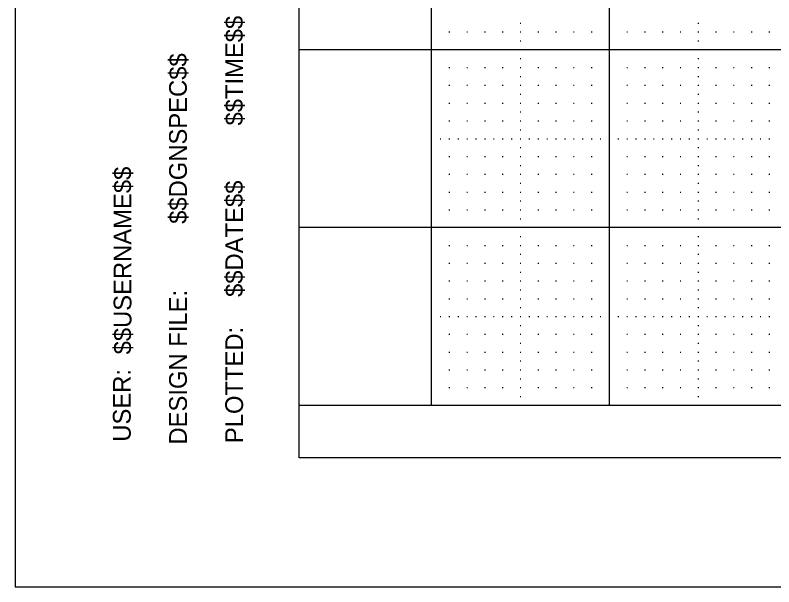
# Model space of a CAD drawing. Extents: x -1.6 to 32.4, y -0.7 to 21.3.
# Drawn here: x -1.598 to 2.67, y -0.727 to 2.487 of the extents above; entities that cross this region are included whole.
import ezdxf

# ---------------------------------------------------------------- set-up
doc = ezdxf.new("R2010")
doc.units = 0
for name, color, linetype in [('Level 1', 7, 'Continuous'), ('Level 4', 7, 'Continuous'), ('Level 5', 7, 'Continuous'), ('Level 63', 7, 'Continuous'), ('R_Border_Dark', 7, 'Continuous')]:
    doc.layers.add(name, color=color, linetype=linetype)

msp = doc.modelspace()

# ---------------------------------------------------------------- linework, layer by layer
at = {"layer": 'Level 1'}
for p, q in [((-0.001, -0.001), (-0.001, 20.545)), ((31.617, -0.001), (-0.001, -0.001))]:
    msp.add_line(p, q, dxfattribs=at)
at = {"layer": 'Level 4'}
msp.add_line((31.617, 0.293), (-0.001, 0.293), dxfattribs=at)
at = {"layer": 'Level 5'}
for p, q in [((1.2425, 2.443), (1.2475, 2.443)), ((2.2425, 2.443), (2.2475, 2.443)), ((0.8425, 2.393), (0.8475, 2.393)), ((0.9425, 2.393), (0.9475, 2.393)), ((1.0425, 2.393), (1.0475, 2.393)), ((1.1425, 2.393), (1.1475, 2.393)), ((1.2425, 2.393), (1.2475, 2.393)), ((1.3425, 2.393), (1.3475, 2.393)), ((1.4425, 2.393), (1.4475, 2.393)), ((1.5425, 2.393), (1.5475, 2.393)), ((1.6425, 2.393), (1.6475, 2.393)), ((1.8425, 2.393), (1.8475, 2.393)), ((1.9425, 2.393), (1.9475, 2.393)), ((2.0425, 2.393), (2.0475, 2.393)), ((2.1425, 2.393), (2.1475, 2.393)), ((2.2425, 2.393), (2.2475, 2.393)), ((2.3425, 2.393), (2.3475, 2.393)), ((2.4425, 2.393), (2.4475, 2.393)), ((2.5425, 2.393), (2.5475, 2.393)), ((2.6425, 2.393), (2.6475, 2.393)), ((1.2425, 2.343), (1.2475, 2.343)), ((2.2425, 2.343), (2.2475, 2.343)), ((1.2425, 2.243), (1.2475, 2.243)), ((2.2425, 2.243), (2.2475, 2.243)), ((0.8425, 2.193), (0.8475, 2.193)), ((0.9425, 2.193), (0.9475, 2.193)), ((1.0425, 2.193), (1.0475, 2.193)), ((1.1425, 2.193), (1.1475, 2.193)), ((1.2425, 2.193), (1.2475, 2.193)), ((1.3425, 2.193), (1.3475, 2.193)), ((1.4425, 2.193), (1.4475, 2.193)), ((1.5425, 2.193), (1.5475, 2.193)), ((1.6425, 2.193), (1.6475, 2.193)), ((1.8425, 2.193), (1.8475, 2.193)), ((1.9425, 2.193), (1.9475, 2.193)), ((2.0425, 2.193), (2.0475, 2.193)), ((2.1425, 2.193), (2.1475, 2.193)), ((2.2425, 2.193), (2.2475, 2.193)), ((2.3425, 2.193), (2.3475, 2.193)), ((2.4425, 2.193), (2.4475, 2.193)), ((2.5425, 2.193), (2.5475, 2.193)), ((2.6425, 2.193), (2.6475, 2.193)), ((1.2425, 2.143), (1.2475, 2.143)), ((2.2425, 2.143), (2.2475, 2.143)), ((0.8425, 2.093), (0.8475, 2.093)), ((0.9425, 2.093), (0.9475, 2.093)), ((1.0425, 2.093), (1.0475, 2.093)), ((1.1425, 2.093), (1.1475, 2.093)), ((1.2425, 2.093), (1.2475, 2.093)), ((1.3425, 2.093), (1.3475, 2.093)), ((1.4425, 2.093), (1.4475, 2.093)), ((1.5425, 2.093), (1.5475, 2.093)), ((1.6425, 2.093), (1.6475, 2.093)), ((1.8425, 2.093), (1.8475, 2.093)), ((1.9425, 2.093), (1.9475, 2.093)), ((2.0425, 2.093), (2.0475, 2.093)), ((2.1425, 2.093), (2.1475, 2.093)), ((2.2425, 2.093), (2.2475, 2.093)), ((2.3425, 2.093), (2.3475, 2.093)), ((2.4425, 2.093), (2.4475, 2.093)), ((2.5425, 2.093), (2.5475, 2.093)), ((2.6425, 2.093), (2.6475, 2.093)), ((1.2425, 2.043), (1.2475, 2.043)), ((2.2425, 2.043), (2.2475, 2.043)), ((0.8425, 1.993), (0.8475, 1.993)), ((0.9425, 1.993), (0.9475, 1.993)), ((1.0425, 1.993), (1.0475, 1.993)), ((1.1425, 1.993), (1.1475, 1.993)), ((1.2425, 1.993), (1.2475, 1.993)), ((1.3425, 1.993), (1.3475, 1.993)), ((1.4425, 1.993), (1.4475, 1.993)), ((1.5425, 1.993), (1.5475, 1.993)), ((1.6425, 1.993), (1.6475, 1.993)), ((1.8425, 1.993), (1.8475, 1.993)), ((1.9425, 1.993), (1.9475, 1.993)), ((2.0425, 1.993), (2.0475, 1.993)), ((2.1425, 1.993), (2.1475, 1.993)), ((2.2425, 1.993), (2.2475, 1.993)), ((2.3425, 1.993), (2.3475, 1.993)), ((2.4425, 1.993), (2.4475, 1.993)), ((2.5425, 1.993), (2.5475, 1.993)), ((2.6425, 1.993), (2.6475, 1.993)), ((1.2425, 1.943), (1.2475, 1.943)), ((2.2425, 1.943), (2.2475, 1.943)), ((0.8425, 1.893), (0.8475, 1.893)), ((0.9425, 1.893), (0.9475, 1.893)), ((1.0425, 1.893), (1.0475, 1.893)), ((1.1425, 1.893), (1.1475, 1.893)), ((1.2425, 1.893), (1.2475, 1.893)), ((1.3425, 1.893), (1.3475, 1.893)), ((1.4425, 1.893), (1.4475, 1.893)), ((1.5425, 1.893), (1.5475, 1.893)), ((1.6425, 1.893), (1.6475, 1.893)), ((1.8425, 1.893), (1.8475, 1.893)), ((1.9425, 1.893), (1.9475, 1.893)), ((2.0425, 1.893), (2.0475, 1.893)), ((2.1425, 1.893), (2.1475, 1.893)), ((2.2425, 1.893), (2.2475, 1.893)), ((2.3425, 1.893), (2.3475, 1.893)), ((2.4425, 1.893), (2.4475, 1.893)), ((2.5425, 1.893), (2.5475, 1.893)), ((2.6425, 1.893), (2.6475, 1.893)), ((1.2425, 1.843), (1.2475, 1.843)), ((2.2425, 1.843), (2.2475, 1.843)), ((0.7925, 1.793), (0.7975, 1.793)), ((0.8425, 1.793), (0.8475, 1.793)), ((0.8925, 1.793), (0.8975, 1.793)), ((0.9425, 1.793), (0.9475, 1.793)), ((0.9925, 1.793), (0.9975, 1.793)), ((1.0425, 1.793), (1.0475, 1.793)), ((1.0925, 1.793), (1.0975, 1.793)), ((1.1425, 1.793), (1.1475, 1.793)), ((1.1925, 1.793), (1.1975, 1.793)), ((1.2425, 1.793), (1.2475, 1.793)), ((1.2925, 1.793), (1.2975, 1.793)), ((1.3425, 1.793), (1.3475, 1.793)), ((1.3925, 1.793), (1.3975, 1.793)), ((1.4425, 1.793), (1.4475, 1.793)), ((1.4925, 1.793), (1.4975, 1.793)), ((1.5425, 1.793), (1.5475, 1.793)), ((1.5925, 1.793), (1.5975, 1.793)), ((1.6425, 1.793), (1.6475, 1.793)), ((1.6925, 1.793), (1.6975, 1.793)), ((1.7925, 1.793), (1.7975, 1.793)), ((1.8425, 1.793), (1.8475, 1.793)), ((1.8925, 1.793), (1.8975, 1.793)), ((1.9425, 1.793), (1.9475, 1.793)), ((1.9925, 1.793), (1.9975, 1.793)), ((2.0425, 1.793), (2.0475, 1.793)), ((2.0925, 1.793), (2.0975, 1.793)), ((2.1425, 1.793), (2.1475, 1.793)), ((2.1925, 1.793), (2.1975, 1.793)), ((2.2425, 1.793), (2.2475, 1.793)), ((2.2925, 1.793), (2.2975, 1.793)), ((2.3425, 1.793), (2.3475, 1.793)), ((2.3925, 1.793), (2.3975, 1.793)), ((2.4425, 1.793), (2.4475, 1.793)), ((2.4925, 1.793), (2.4975, 1.793)), ((2.5425, 1.793), (2.5475, 1.793)), ((2.5925, 1.793), (2.5975, 1.793)), ((2.6425, 1.793), (2.6475, 1.793)), ((1.2425, 1.743), (1.2475, 1.743)), ((2.2425, 1.743), (2.2475, 1.743)), ((0.8425, 1.693), (0.8475, 1.693)), ((0.9425, 1.693), (0.9475, 1.693)), ((1.0425, 1.693), (1.0475, 1.693)), ((1.1425, 1.693), (1.1475, 1.693)), ((1.2425, 1.693), (1.2475, 1.693)), ((1.3425, 1.693), (1.3475, 1.693)), ((1.4425, 1.693), (1.4475, 1.693)), ((1.5425, 1.693), (1.5475, 1.693)), ((1.6425, 1.693), (1.6475, 1.693)), ((1.8425, 1.693), (1.8475, 1.693)), ((1.9425, 1.693), (1.9475, 1.693)), ((2.0425, 1.693), (2.0475, 1.693)), ((2.1425, 1.693), (2.1475, 1.693)), ((2.2425, 1.693), (2.2475, 1.693)), ((2.3425, 1.693), (2.3475, 1.693)), ((2.4425, 1.693), (2.4475, 1.693)), ((2.5425, 1.693), (2.5475, 1.693)), ((2.6425, 1.693), (2.6475, 1.693)), ((1.2425, 1.643), (1.2475, 1.643)), ((2.2425, 1.643), (2.2475, 1.643)), ((0.8425, 1.593), (0.8475, 1.593)), ((0.9425, 1.593), (0.9475, 1.593)), ((1.0425, 1.593), (1.0475, 1.593)), ((1.1425, 1.593), (1.1475, 1.593)), ((1.2425, 1.593), (1.2475, 1.593)), ((1.3425, 1.593), (1.3475, 1.593)), ((1.4425, 1.593), (1.4475, 1.593)), ((1.5425, 1.593), (1.5475, 1.593)), ((1.6425, 1.593), (1.6475, 1.593)), ((1.8425, 1.593), (1.8475, 1.593)), ((1.9425, 1.593), (1.9475, 1.593)), ((2.0425, 1.593), (2.0475, 1.593)), ((2.1425, 1.593), (2.1475, 1.593)), ((2.2425, 1.593), (2.2475, 1.593)), ((2.3425, 1.593), (2.3475, 1.593)), ((2.4425, 1.593), (2.4475, 1.593)), ((2.5425, 1.593), (2.5475, 1.593)), ((2.6425, 1.593), (2.6475, 1.593)), ((1.2425, 1.543), (1.2475, 1.543)), ((2.2425, 1.543), (2.2475, 1.543)), ((0.8425, 1.493), (0.8475, 1.493)), ((0.9425, 1.493), (0.9475, 1.493)), ((1.0425, 1.493), (1.0475, 1.493)), ((1.1425, 1.493), (1.1475, 1.493)), ((1.2425, 1.493), (1.2475, 1.493)), ((1.3425, 1.493), (1.3475, 1.493)), ((1.4425, 1.493), (1.4475, 1.493)), ((1.5425, 1.493), (1.5475, 1.493)), ((1.6425, 1.493), (1.6475, 1.493)), ((1.8425, 1.493), (1.8475, 1.493)), ((1.9425, 1.493), (1.9475, 1.493)), ((2.0425, 1.493), (2.0475, 1.493)), ((2.1425, 1.493), (2.1475, 1.493)), ((2.2425, 1.493), (2.2475, 1.493)), ((2.3425, 1.493), (2.3475, 1.493)), ((2.4425, 1.493), (2.4475, 1.493)), ((2.5425, 1.493), (2.5475, 1.493)), ((2.6425, 1.493), (2.6475, 1.493)), ((1.2425, 1.443), (1.2475, 1.443)), ((2.2425, 1.443), (2.2475, 1.443)), ((0.8425, 1.393), (0.8475, 1.393)), ((0.9425, 1.393), (0.9475, 1.393)), ((1.0425, 1.393), (1.0475, 1.393)), ((1.1425, 1.393), (1.1475, 1.393)), ((1.2425, 1.393), (1.2475, 1.393)), ((1.3425, 1.393), (1.3475, 1.393)), ((1.4425, 1.393), (1.4475, 1.393)), ((1.5425, 1.393), (1.5475, 1.393)), ((1.6425, 1.393), (1.6475, 1.393)), ((1.8425, 1.393), (1.8475, 1.393)), ((1.9425, 1.393), (1.9475, 1.393)), ((2.0425, 1.393), (2.0475, 1.393)), ((2.1425, 1.393), (2.1475, 1.393)), ((2.2425, 1.393), (2.2475, 1.393)), ((2.3425, 1.393), (2.3475, 1.393)), ((2.4425, 1.393), (2.4475, 1.393)), ((2.5425, 1.393), (2.5475, 1.393)), ((2.6425, 1.393), (2.6475, 1.393)), ((1.2425, 1.343), (1.2475, 1.343)), ((2.2425, 1.343), (2.2475, 1.343)), ((1.2425, 1.243), (1.2475, 1.243)), ((2.2425, 1.243), (2.2475, 1.243)), ((0.8425, 1.193), (0.8475, 1.193)), ((0.9425, 1.193), (0.9475, 1.193)), ((1.0425, 1.193), (1.0475, 1.193)), ((1.1425, 1.193), (1.1475, 1.193)), ((1.2425, 1.193), (1.2475, 1.193)), ((1.3425, 1.193), (1.3475, 1.193)), ((1.4425, 1.193), (1.4475, 1.193)), ((1.5425, 1.193), (1.5475, 1.193)), ((1.6425, 1.193), (1.6475, 1.193)), ((1.8425, 1.193), (1.8475, 1.193)), ((1.9425, 1.193), (1.9475, 1.193)), ((2.0425, 1.193), (2.0475, 1.193)), ((2.1425, 1.193), (2.1475, 1.193)), ((2.2425, 1.193), (2.2475, 1.193)), ((2.3425, 1.193), (2.3475, 1.193)), ((2.4425, 1.193), (2.4475, 1.193)), ((2.5425, 1.193), (2.5475, 1.193)), ((2.6425, 1.193), (2.6475, 1.193)), ((1.2425, 1.143), (1.2475, 1.143)), ((2.2425, 1.143), (2.2475, 1.143)), ((0.8425, 1.093), (0.8475, 1.093)), ((0.9425, 1.093), (0.9475, 1.093)), ((1.0425, 1.093), (1.0475, 1.093)), ((1.1425, 1.093), (1.1475, 1.093)), ((1.2425, 1.093), (1.2475, 1.093)), ((1.3425, 1.093), (1.3475, 1.093)), ((1.4425, 1.093), (1.4475, 1.093)), ((1.5425, 1.093), (1.5475, 1.093)), ((1.6425, 1.093), (1.6475, 1.093)), ((1.8425, 1.093), (1.8475, 1.093)), ((1.9425, 1.093), (1.9475, 1.093)), ((2.0425, 1.093), (2.0475, 1.093)), ((2.1425, 1.093), (2.1475, 1.093)), ((2.2425, 1.093), (2.2475, 1.093)), ((2.3425, 1.093), (2.3475, 1.093)), ((2.4425, 1.093), (2.4475, 1.093)), ((2.5425, 1.093), (2.5475, 1.093)), ((2.6425, 1.093), (2.6475, 1.093)), ((1.2425, 1.043), (1.2475, 1.043)), ((2.2425, 1.043), (2.2475, 1.043)), ((0.8425, 0.993), (0.8475, 0.993)), ((0.9425, 0.993), (0.9475, 0.993)), ((1.0425, 0.993), (1.0475, 0.993)), ((1.1425, 0.993), (1.1475, 0.993)), ((1.2425, 0.993), (1.2475, 0.993)), ((1.3425, 0.993), (1.3475, 0.993)), ((1.4425, 0.993), (1.4475, 0.993)), ((1.5425, 0.993), (1.5475, 0.993)), ((1.6425, 0.993), (1.6475, 0.993)), ((1.8425, 0.993), (1.8475, 0.993)), ((1.9425, 0.993), (1.9475, 0.993)), ((2.0425, 0.993), (2.0475, 0.993)), ((2.1425, 0.993), (2.1475, 0.993)), ((2.2425, 0.993), (2.2475, 0.993)), ((2.3425, 0.993), (2.3475, 0.993)), ((2.4425, 0.993), (2.4475, 0.993)), ((2.5425, 0.993), (2.5475, 0.993)), ((2.6425, 0.993), (2.6475, 0.993)), ((1.2425, 0.943), (1.2475, 0.943)), ((2.2425, 0.943), (2.2475, 0.943)), ((0.8425, 0.893), (0.8475, 0.893)), ((0.9425, 0.893), (0.9475, 0.893)), ((1.0425, 0.893), (1.0475, 0.893)), ((1.1425, 0.893), (1.1475, 0.893)), ((1.2425, 0.893), (1.2475, 0.893)), ((1.3425, 0.893), (1.3475, 0.893)), ((1.4425, 0.893), (1.4475, 0.893)), ((1.5425, 0.893), (1.5475, 0.893)), ((1.6425, 0.893), (1.6475, 0.893)), ((1.8425, 0.893), (1.8475, 0.893)), ((1.9425, 0.893), (1.9475, 0.893)), ((2.0425, 0.893), (2.0475, 0.893)), ((2.1425, 0.893), (2.1475, 0.893)), ((2.2425, 0.893), (2.2475, 0.893)), ((2.3425, 0.893), (2.3475, 0.893)), ((2.4425, 0.893), (2.4475, 0.893)), ((2.5425, 0.893), (2.5475, 0.893)), ((2.6425, 0.893), (2.6475, 0.893)), ((1.2425, 0.843), (1.2475, 0.843)), ((2.2425, 0.843), (2.2475, 0.843)), ((0.7925, 0.793), (0.7975, 0.793)), ((0.8425, 0.793), (0.8475, 0.793)), ((0.8925, 0.793), (0.8975, 0.793)), ((0.9425, 0.793), (0.9475, 0.793)), ((0.9925, 0.793), (0.9975, 0.793)), ((1.0425, 0.793), (1.0475, 0.793)), ((1.0925, 0.793), (1.0975, 0.793)), ((1.1425, 0.793), (1.1475, 0.793)), ((1.1925, 0.793), (1.1975, 0.793)), ((1.2425, 0.793), (1.2475, 0.793)), ((1.2925, 0.793), (1.2975, 0.793)), ((1.3425, 0.793), (1.3475, 0.793)), ((1.3925, 0.793), (1.3975, 0.793)), ((1.4425, 0.793), (1.4475, 0.793)), ((1.4925, 0.793), (1.4975, 0.793)), ((1.5425, 0.793), (1.5475, 0.793)), ((1.5925, 0.793), (1.5975, 0.793)), ((1.6425, 0.793), (1.6475, 0.793)), ((1.6925, 0.793), (1.6975, 0.793)), ((1.7925, 0.793), (1.7975, 0.793)), ((1.8425, 0.793), (1.8475, 0.793)), ((1.8925, 0.793), (1.8975, 0.793)), ((1.9425, 0.793), (1.9475, 0.793)), ((1.9925, 0.793), (1.9975, 0.793)), ((2.0425, 0.793), (2.0475, 0.793)), ((2.0925, 0.793), (2.0975, 0.793)), ((2.1425, 0.793), (2.1475, 0.793)), ((2.1925, 0.793), (2.1975, 0.793)), ((2.2425, 0.793), (2.2475, 0.793)), ((2.2925, 0.793), (2.2975, 0.793)), ((2.3425, 0.793), (2.3475, 0.793)), ((2.3925, 0.793), (2.3975, 0.793)), ((2.4425, 0.793), (2.4475, 0.793)), ((2.4925, 0.793), (2.4975, 0.793)), ((2.5425, 0.793), (2.5475, 0.793)), ((2.5925, 0.793), (2.5975, 0.793)), ((2.6425, 0.793), (2.6475, 0.793)), ((1.2425, 0.743), (1.2475, 0.743)), ((2.2425, 0.743), (2.2475, 0.743)), ((0.8425, 0.693), (0.8475, 0.693)), ((0.9425, 0.693), (0.9475, 0.693)), ((1.0425, 0.693), (1.0475, 0.693)), ((1.1425, 0.693), (1.1475, 0.693)), ((1.2425, 0.693), (1.2475, 0.693)), ((1.3425, 0.693), (1.3475, 0.693)), ((1.4425, 0.693), (1.4475, 0.693)), ((1.5425, 0.693), (1.5475, 0.693)), ((1.6425, 0.693), (1.6475, 0.693)), ((1.8425, 0.693), (1.8475, 0.693)), ((1.9425, 0.693), (1.9475, 0.693)), ((2.0425, 0.693), (2.0475, 0.693)), ((2.1425, 0.693), (2.1475, 0.693)), ((2.2425, 0.693), (2.2475, 0.693)), ((2.3425, 0.693), (2.3475, 0.693)), ((2.4425, 0.693), (2.4475, 0.693)), ((2.5425, 0.693), (2.5475, 0.693)), ((2.6425, 0.693), (2.6475, 0.693)), ((1.2425, 0.643), (1.2475, 0.643)), ((2.2425, 0.643), (2.2475, 0.643)), ((0.8425, 0.593), (0.8475, 0.593)), ((0.9425, 0.593), (0.9475, 0.593)), ((1.0425, 0.593), (1.0475, 0.593)), ((1.1425, 0.593), (1.1475, 0.593)), ((1.2425, 0.593), (1.2475, 0.593)), ((1.3425, 0.593), (1.3475, 0.593)), ((1.4425, 0.593), (1.4475, 0.593)), ((1.5425, 0.593), (1.5475, 0.593)), ((1.6425, 0.593), (1.6475, 0.593)), ((1.8425, 0.593), (1.8475, 0.593)), ((1.9425, 0.593), (1.9475, 0.593)), ((2.0425, 0.593), (2.0475, 0.593)), ((2.1425, 0.593), (2.1475, 0.593)), ((2.2425, 0.593), (2.2475, 0.593)), ((2.3425, 0.593), (2.3475, 0.593)), ((2.4425, 0.593), (2.4475, 0.593)), ((2.5425, 0.593), (2.5475, 0.593)), ((2.6425, 0.593), (2.6475, 0.593)), ((1.2425, 0.543), (1.2475, 0.543)), ((2.2425, 0.543), (2.2475, 0.543)), ((0.8425, 0.493), (0.8475, 0.493)), ((0.9425, 0.493), (0.9475, 0.493)), ((1.0425, 0.493), (1.0475, 0.493)), ((1.1425, 0.493), (1.1475, 0.493)), ((1.2425, 0.493), (1.2475, 0.493)), ((1.3425, 0.493), (1.3475, 0.493)), ((1.4425, 0.493), (1.4475, 0.493)), ((1.5425, 0.493), (1.5475, 0.493)), ((1.6425, 0.493), (1.6475, 0.493)), ((1.8425, 0.493), (1.8475, 0.493)), ((1.9425, 0.493), (1.9475, 0.493)), ((2.0425, 0.493), (2.0475, 0.493)), ((2.1425, 0.493), (2.1475, 0.493)), ((2.2425, 0.493), (2.2475, 0.493)), ((2.3425, 0.493), (2.3475, 0.493)), ((2.4425, 0.493), (2.4475, 0.493)), ((2.5425, 0.493), (2.5475, 0.493)), ((2.6425, 0.493), (2.6475, 0.493)), ((1.2425, 0.443), (1.2475, 0.443)), ((2.2425, 0.443), (2.2475, 0.443)), ((0.8425, 0.393), (0.8475, 0.393)), ((0.9425, 0.393), (0.9475, 0.393)), ((1.0425, 0.393), (1.0475, 0.393)), ((1.1425, 0.393), (1.1475, 0.393)), ((1.2425, 0.393), (1.2475, 0.393)), ((1.3425, 0.393), (1.3475, 0.393)), ((1.4425, 0.393), (1.4475, 0.393)), ((1.5425, 0.393), (1.5475, 0.393)), ((1.6425, 0.393), (1.6475, 0.393)), ((1.8425, 0.393), (1.8475, 0.393)), ((1.9425, 0.393), (1.9475, 0.393)), ((2.0425, 0.393), (2.0475, 0.393)), ((2.1425, 0.393), (2.1475, 0.393)), ((2.2425, 0.393), (2.2475, 0.393)), ((2.3425, 0.393), (2.3475, 0.393)), ((2.4425, 0.393), (2.4475, 0.393)), ((2.5425, 0.393), (2.5475, 0.393)), ((2.6425, 0.393), (2.6475, 0.393)), ((1.2425, 0.343), (1.2475, 0.343)), ((2.2425, 0.343), (2.2475, 0.343))]:
    msp.add_line(p, q, dxfattribs=at)
at = {"layer": 'Level 63'}
msp.add_lwpolyline([(-1.598, -0.727), (32.402, -0.727), (32.402, 21.273), (-1.598, 21.273)], close=True, dxfattribs=at)
msp.add_lwpolyline([(30.745, 8.293), (30.745, 0.293), (0.745, 0.293), (0.745, 8.293)], dxfattribs=at)
at = {"layer": 'R_Border_Dark'}
for p, q in [((0.745, 0.293), (0.745, 8.293)), ((1.745, 0.293), (1.745, 8.293)), ((31.617, 2.293), (-0.001, 2.293)), ((31.617, 1.293), (-0.001, 1.293))]:
    msp.add_line(p, q, dxfattribs=at)
msp.add_lwpolyline([(30.745, 8.293), (30.745, 0.293), (0.745, 0.293), (0.745, 8.293)], dxfattribs=at)

# ---------------------------------------------------------------- texts
at = {"layer": 'Level 1'}
for s, height, p in [('$$TIME$$', 0.1, (-0.316, 1.867)), ('$$DGNSPEC$$', 0.100002, (-0.632, 1.314)), ('$$USERNAME$$', 0.100002, (-0.944, 0.58)), ('$$DATE$$', 0.1, (-0.316, 0.903)), ('DESIGN FILE:', 0.100002, (-0.632, 0.073)), ('PLOTTED:', 0.1, (-0.316, 0.081)), ('USER:', 0.1, (-0.948, 0.089))]:
    msp.add_text(s, height=height, rotation=90, dxfattribs=at).set_placement(p)

doc.saveas('drawing.dxf')
